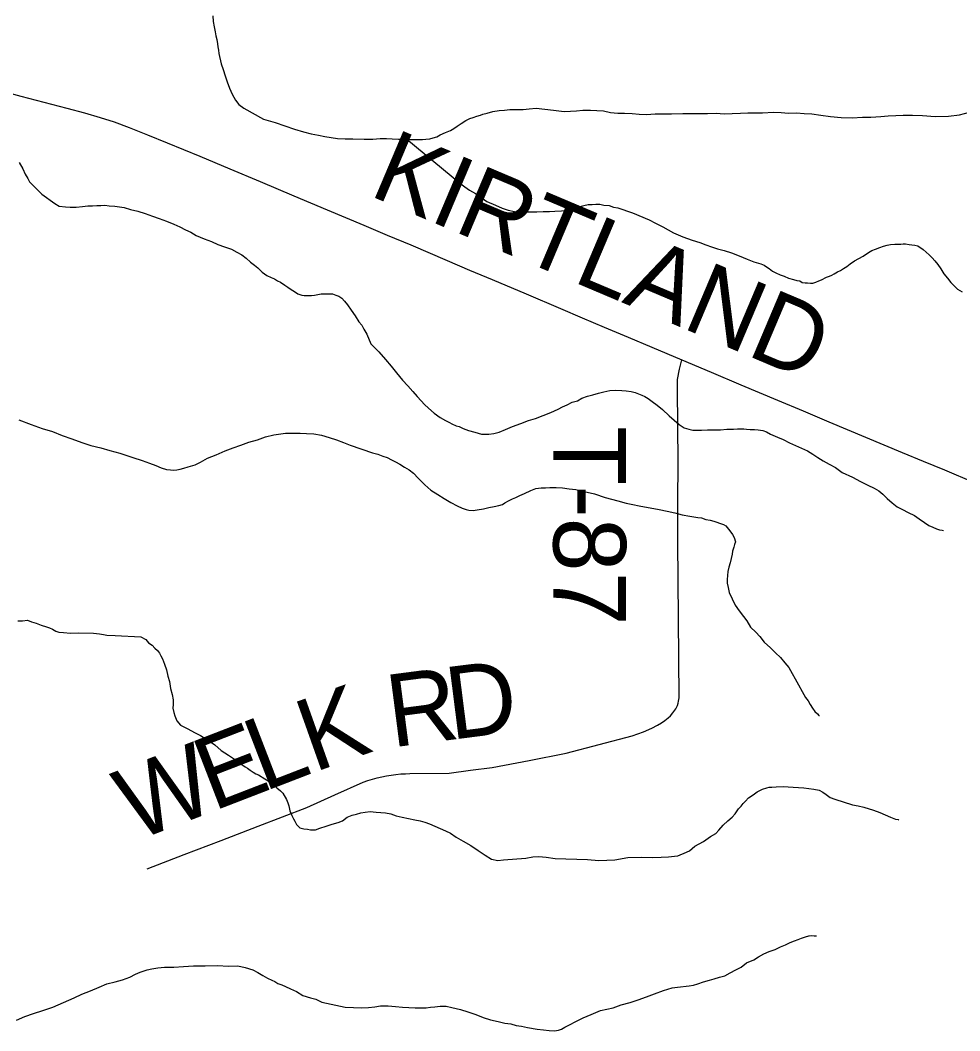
# Model space of a CAD drawing. Extents: x 103424 to 286016, y 38711 to 110967.
# Drawn here: x 120420 to 124329, y 102278 to 106482 of the extents above; entities that cross this region are included whole.
import ezdxf

# ---------------------------------------------------------------- set-up
doc = ezdxf.new("R2010")
doc.units = 0
for name, color, linetype in [('GM_X_County_Road', 7, 'Continuous'), ('GM_X_County_Road_Text', 7, 'Continuous'), ('GM_X_Minor_River', 7, 'Continuous'), ('GM_X_Township_Road', 7, 'Continuous'), ('GM_X_Township_Road_Text', 7, 'Continuous')]:
    doc.layers.add(name, color=color, linetype=linetype)

msp = doc.modelspace()

# ---------------------------------------------------------------- linework, layer by layer
at = {"layer": 'GM_X_County_Road'}
msp.add_lwpolyline([(120309.2, 106195.9), (120423.4, 106166), (120518.9, 106141.2), (120614.3, 106116.3), (120687.6, 106096.5), (120752.3, 106077.6), (120811.6, 106058.5), (120873.7, 106034.9), (120949.3, 106004.4), (121031.4, 105971.4), (121167, 105916.1), (121292.6, 105863.2), (121418.1, 105810.4), (121558, 105751.8), (121697.9, 105693.1), (121850, 105629.1), (121947.5, 105588.1), (122045.1, 105547), (122196.9, 105482.3), (122290, 105442.6), (122383.1, 105402.9), (122525.3, 105343), (122667.4, 105283), (122758.8, 105244), (122850.2, 105205.1), (122949, 105163.6), (123047.9, 105122.1), (123172.5, 105069.5), (123295.3, 105017.4), (123418.2, 104965.3), (123570.4, 104901.4), (123677.7, 104856.4), (123785, 104811.3), (123937.3, 104747.8), (124089.7, 104684.2), (124177.4, 104647.5), (124265.2, 104610.9), (124389, 104559.2)], dxfattribs=at)
at = {"layer": 'GM_X_Minor_River'}
for points in [[(121221, 106499.9), (121223.3, 106475.6), (121227.6, 106453.5), (121231.8, 106433.3), (121234, 106417.2), (121238.3, 106401), (121240.5, 106382.9), (121242.7, 106370.8), (121244.8, 106356.7), (121247, 106342.6), (121255.6, 106300.2), (121264, 106276.1), (121272.3, 106249.9), (121280.7, 106225.8), (121291.1, 106199.6), (121301.5, 106173.4), (121315.9, 106149.3), (121330.3, 106131.3), (121350.6, 106115.4), (121432, 106069.7), (121480.6, 106056.1), (121521.2, 106042.3), (121561.7, 106028.6), (121598.2, 106016.8), (121630.6, 106009.1), (121661, 106003.3), (121687.3, 105997.5), (121713.6, 105993.7), (121739.9, 105989.9), (121772.2, 105988.2), (121804.6, 105988.6), (121851, 105987), (121887.4, 105987.4), (121917.7, 105989.7), (121943.9, 105990), (121968.2, 105988.2), (121994.5, 105986.4), (122014.6, 105986.6), (122028.8, 105986.8), (122038.9, 105984.8), (122057.1, 105985), (122073.2, 105985.2), (122093.4, 105985.4), (122107.5, 105987.5), (122123.7, 105987.7), (122137.8, 105991.9), (122153.9, 105996.1), (122167.9, 106004.3), (122190, 106014.6), (122210.1, 106022.9), (122224.2, 106031.1), (122238.2, 106041.4), (122254.3, 106051.6), (122274.3, 106063.9), (122290.4, 106072.2), (122304.5, 106076.4), (122320.5, 106082.6), (122334.6, 106086.8), (122344.7, 106090.9), (122362.8, 106095.1), (122387, 106101.4), (122413.2, 106105.7), (122435.4, 106108), (122457.6, 106110.2), (122479.8, 106110.4), (122512.1, 106110.7), (122538.3, 106113), (122566.6, 106115.3), (122639.4, 106108), (122661.6, 106104.1), (122683.9, 106102.3), (122710.1, 106102.6)], [(122710.1, 106102.6), (122734.3, 106104.9), (122760.6, 106107.2), (122792.9, 106107.5), (122819.2, 106105.7), (122847.5, 106104), (122875.8, 106098.2), (122906.2, 106094.5), (122934.4, 106094.8), (122966.8, 106093), (122995.1, 106091.3), (123025.4, 106089.6), (123061.7, 106092), (123096, 106092.3), (123130.4, 106092.7), (123176.8, 106093.1), (123211.2, 106093.5), (123245.5, 106093.8), (123279.8, 106094.1), (123316.2, 106094.5), (123348.5, 106092.8), (123382.8, 106093.2), (123417.1, 106095.5), (123447.4, 106095.8), (123475.7, 106096.1), (123508, 106096.4), (123554.4, 106098.9), (123586.8, 106097.2), (123617.1, 106095.5), (123649.4, 106095.8), (123681.8, 106094.1), (123714.1, 106092.4), (123750.5, 106086.7), (123791, 106081.1), (123835.5, 106077.5), (123881.9, 106075.9), (123924.3, 106078.3), (123958.6, 106078.7), (124001, 106081.1), (124031.3, 106083.5), (124063.6, 106085.8), (124093.9, 106086.1), (124132.3, 106086.5), (124174.7, 106084.9), (124227.3, 106081.4), (124281.8, 106081.9), (124328.2, 106088.4), (124390.6, 106105.2)], [(122028.8, 105986.8), (122253.1, 105801.1), (122269.4, 105789.2), (122289.8, 105775.2), (122314.2, 105761.4), (122336.6, 105745.4), (122361, 105727.5), (122397.6, 105711.7), (122426, 105699.9), (122450.3, 105692), (122476.6, 105686.2), (122498.9, 105684.4), (122521.1, 105684.6), (122543.3, 105684.9), (122569.6, 105685.1), (122595.8, 105685.4), (122622.1, 105685.6), (122644.3, 105687.9), (122672.5, 105688.2), (122690.7, 105690.4), (122706.8, 105694.6), (122718.9, 105698.7), (122733, 105702.9), (122749.1, 105707.1), (122765.2, 105711.3), (122783.3, 105715.5), (122799.5, 105715.7), (122815.6, 105715.9), (122831.8, 105716), (122848, 105712.1), (122870.2, 105710.3), (122888.5, 105704.5), (122906.7, 105700.6), (122927, 105694.7), (122947.2, 105686.9), (122967.5, 105681), (123036.5, 105651.4), (123062.9, 105637.5), (123093.4, 105621.7), (123138.1, 105597.9), (123176.7, 105580.1), (123215.3, 105566.3), (123247.7, 105556.5), (123272, 105546.7), (123296.4, 105538.8), (123320.7, 105531), (123349.1, 105523.2), (123379.5, 105513.4), (123411.9, 105501.6), (123444.4, 105487.8), (123472.8, 105476), (123501.2, 105468.2), (123515.4, 105462.2), (123525.6, 105456.3), (123535.7, 105448.3), (123550, 105438.4), (123564.2, 105430.4), (123582.5, 105422.5), (123598.7, 105416.6), (123617, 105408.7), (123637.3, 105402.9), (123651.5, 105399), (123663.6, 105397.1), (123673.8, 105391.1), (123685.9, 105389.2), (123696, 105389.3), (123708.1, 105387.4), (123718.2, 105387.5), (123730.3, 105391.7), (123742.4, 105397.8), (123754.4, 105402), (123774.5, 105412.3), (123786.6, 105416.5), (123796.6, 105420.6), (123806.7, 105426.8), (123820.7, 105435), (123832.7, 105441.2), (123844.8, 105449.4), (123858.8, 105457.6), (123872.8, 105467.8), (123890.9, 105480.1), (123927, 105500.7), (123949, 105515), (123963.1, 105523.3), (123979.2, 105529.5), (123997.3, 105535.7), (124011.3, 105541.9), (124027.4, 105546.1), (124041.6, 105548.3), (124059.7, 105550.5), (124071.8, 105550.6), (124083.9, 105550.7), (124094, 105550.8), (124104.1, 105550.9), (124118.3, 105549), (124130.4, 105547.1), (124142.6, 105545.3), (124154.7, 105543.4)], [(120416.1, 105890), (120430.5, 105863.8), (120440.9, 105841.7), (120451.2, 105823.6), (120459.4, 105809.6), (120469.7, 105797.6), (120481.9, 105785.6), (120496.2, 105771.6), (120510.5, 105757.6), (120563.5, 105719.7), (120581.8, 105707.8), (120608.1, 105706), (120628.3, 105704.2), (120652.5, 105704.5), (120678.8, 105706.7), (120701, 105709), (120721.2, 105709.2), (120739.3, 105711.4), (120755.5, 105711.5), (120771.6, 105711.7), (120789.8, 105709.9), (120814.1, 105708.1), (120852.5, 105702.4), (120878.9, 105694.6), (120909.3, 105686.8), (120939.7, 105677), (120970.1, 105667.2), (120998.5, 105657.4), (121028.9, 105645.6), (121059.3, 105633.8), (121083.7, 105621.9), (121108.1, 105610), (121130.4, 105600.1), (121152.8, 105586.2), (121185.3, 105572.4), (121215.7, 105560.6), (121242.1, 105548.7), (121270.5, 105538.9), (121298.9, 105529.1), (121321.2, 105517.2), (121341.6, 105505.3), (121359.9, 105491.3), (121378.3, 105475.3), (121394.6, 105463.4), (121408.9, 105451.4), (121427.3, 105433.4), (121445.6, 105419.4), (121463.9, 105411.5), (121478.1, 105405.6), (121490.3, 105397.7), (121502.5, 105391.7), (121520.8, 105379.8), (121533, 105371.8), (121547.3, 105361.9), (121561.5, 105353.9), (121575.7, 105344), (121592, 105338.1), (121602.1, 105336.2), (121632.4, 105336.5), (121644.5, 105338.6), (121658.6, 105340.8), (121672.7, 105342.9), (121690.9, 105343.1), (121705, 105343.2), (121719.2, 105343.4), (121733.4, 105337.5), (121745.5, 105333.6), (121757.7, 105325.6), (121770, 105313.6), (121782.3, 105297.6), (121796.7, 105275.5), (121813.1, 105251.4), (121829.6, 105227.3), (121841.9, 105213.3), (121850.1, 105197.2)], [(124154.7, 105543.4), (124177.1, 105527.4), (124189.4, 105517.4), (124201.6, 105505.4), (124213.9, 105493.4), (124226.1, 105481.4), (124238.5, 105465.4), (124250.8, 105447.4), (124263.1, 105427.3), (124277.5, 105409.2), (124291.8, 105391.2), (124306.1, 105377.2), (124320.4, 105363.2), (124338.7, 105351.3)], [(121850.1, 105197.2), (121862.5, 105175.1), (121879.1, 105134.9), (121911.8, 105102.9), (121940.5, 105070.9), (121963, 105042.8), (121985.5, 105014.8), (122010.1, 104984.7), (122032.6, 104960.7), (122053.1, 104936.7), (122071.5, 104916.7), (122087.9, 104898.6), (122102.2, 104882.6), (122118.5, 104868.6), (122143, 104846.7), (122167.5, 104828.7), (122189.8, 104816.8), (122206.1, 104808.9), (122216.2, 104803), (122234.5, 104795.1), (122246.7, 104791.1), (122262.9, 104783.2), (122285.2, 104775.4), (122311.6, 104767.6), (122340, 104759.7), (122370.3, 104760.1), (122390.4, 104762.3), (122412.6, 104768.5), (122438.7, 104778.9), (122468.9, 104791.3), (122503, 104803.8), (122535.2, 104816.2), (122563.4, 104824.6), (122627.7, 104849.5), (122657.9, 104863.9), (122675.9, 104874.2), (122696, 104882.5), (122716.1, 104892.8), (122738.3, 104899), (122756.3, 104909.3), (122780.5, 104917.6), (122802.6, 104923.9), (122826.8, 104930.2), (122848.9, 104936.5), (122873.1, 104940.8), (122897.3, 104943), (122923.6, 104941.3), (122941.8, 104939.4), (122962, 104937.6), (122978.2, 104933.8), (122992.4, 104927.8), (123006.6, 104921.9), (123018.8, 104916), (123033, 104908), (123049.3, 104896.1), (123069.7, 104880.1), (123092.1, 104862.2), (123120.7, 104836.2), (123141.1, 104818.2), (123161.5, 104800.2), (123181.9, 104786.3), (123202.2, 104780.5), (123218.4, 104776.6), (123234.5, 104776.7), (123254.7, 104776.9), (123279, 104777.2), (123305.2, 104777.4), (123333.5, 104777.7), (123359.7, 104780), (123388, 104780.3), (123404.1, 104782.5), (123418.3, 104782.6), (123430.4, 104782.7), (123442.5, 104780.8), (123456.7, 104778.9), (123474.9, 104779.1), (123491, 104777.3), (123509.2, 104775.4), (123525.5, 104769.5), (123541.7, 104759.6), (123570.2, 104747.8), (123594.5, 104737.9), (123620.9, 104724), (123696.1, 104690.4), (123718.4, 104676.5), (123738.8, 104662.6), (123761.2, 104648.7), (123785.6, 104634.8), (123812, 104620.9), (123840.5, 104601), (123883.1, 104581.2), (123915.7, 104563.3), (123946.1, 104547.5), (123972.5, 104535.6), (123992.9, 104523.7), (124009.2, 104509.7), (124027.6, 104491.8), (124048, 104473.8), (124068.4, 104457.8), (124090.7, 104445.9), (124115.1, 104434)], [(120414.4, 104819.4), (120465.1, 104799.7), (120511.8, 104784), (120554.3, 104770.3), (120594.9, 104754.5), (120635.5, 104740.8), (120676, 104725), (120714.6, 104713.3), (120755.1, 104703.6), (120793.6, 104691.9), (120834.1, 104680.2), (120888.9, 104662.5), (120927.4, 104650.8), (120957.8, 104639), (120984.2, 104629.1), (121006.5, 104619.3), (121028.8, 104613.4), (121045, 104611.6), (121059.1, 104609.7), (121071.2, 104611.8), (121085.3, 104614), (121101.4, 104618.2), (121119.6, 104624.4), (121147.7, 104632.8), (121169.8, 104643.1), (121199.9, 104659.6), (121236.1, 104674.1), (121272.3, 104690.6), (121306.5, 104703), (121338.7, 104713.4), (121370.8, 104725.9), (121407.1, 104736.3), (121441.3, 104748.8), (121475.5, 104757.2), (121523.9, 104763.8), (121556.2, 104764.1), (121584.5, 104764.4), (121610.8, 104762.6), (121641.1, 104760.9), (121673.5, 104755.1), (121705.9, 104745.4), (121736.3, 104735.6), (121764.7, 104725.8)], [(121764.7, 104725.8), (121793.1, 104713.9), (121886.4, 104682.5), (121908.7, 104676.7), (121929, 104668.8), (121947.2, 104662.9), (121965.5, 104653), (121981.8, 104645.1), (122000.1, 104635.2), (122018.4, 104623.2), (122038.7, 104611.3), (122057, 104597.4), (122075.5, 104577.4), (122104.1, 104549.4), (122128.6, 104527.4), (122157, 104509.5), (122183.5, 104491.6), (122212, 104475.7), (122238.4, 104461.8), (122258.7, 104451.9), (122274.9, 104446), (122287.1, 104444.1), (122305.3, 104442.3), (122321.4, 104444.5), (122347.6, 104448.8), (122369.7, 104455), (122391.9, 104459.3), (122412.1, 104463.5), (122426.2, 104467.7), (122436.2, 104473.9), (122452.2, 104482.1), (122468.3, 104490.4), (122482.4, 104496.6), (122498.4, 104504.8), (122518.5, 104513.1), (122544.7, 104525.5), (122564.8, 104533.7), (122586.9, 104536), (122605.1, 104536.2), (122623.3, 104538.4), (122649.5, 104538.6), (122675.8, 104536.9), (122704.1, 104533.1), (122732.5, 104529.4), (122766.9, 104521.6), (122809.4, 104511.9), (122854, 104496.2), (122906.7, 104482.6), (122941.1, 104472.8), (122969.5, 104467.1), (122995.8, 104461.3), (123078.8, 104445.9), (123111.2, 104440.2), (123143.6, 104432.4), (123174, 104424.7), (123206.4, 104418.9), (123238.8, 104413.2), (123254.9, 104411.3), (123273.2, 104405.4), (123291.4, 104401.6), (123305.6, 104397.7), (123317.8, 104393.8), (123329.9, 104389.9), (123346.1, 104384), (123356.3, 104378), (123372.7, 104358), (123383, 104341.9), (123391.2, 104329.9), (123395.5, 104311.7), (123391.5, 104301.6), (123389.7, 104289.5), (123383.8, 104273.2), (123381.9, 104261.1), (123378.1, 104242.9), (123374.2, 104224.7), (123368.4, 104206.4), (123364.6, 104188.2), (123362.7, 104172), (123360.9, 104155.9), (123361.1, 104139.7), (123365.4, 104121.6), (123369.6, 104101.4), (123382, 104075.3), (123394.5, 104049.1), (123410.9, 104025.1), (123429.4, 104001), (123443.7, 103983), (123458.2, 103956.9), (123480.6, 103936.9), (123497, 103918.9), (123515.4, 103894.8), (123542, 103870.8), (123562.4, 103850.8), (123582.8, 103830.9), (123601.3, 103808.8), (123617.7, 103788.8), (123632.1, 103764.7), (123644.4, 103742.6), (123687.8, 103664.2), (123698, 103650.2), (123706.3, 103636.1)], [(124115.1, 104434), (124141.5, 104422.2), (124159.8, 104408.2), (124182.2, 104392.3), (124200.6, 104380.4), (124216.8, 104372.4), (124233, 104366.5), (124245.2, 104362.6), (124255.3, 104360.7), (124261.4, 104358.7)], [(120410, 103983.1), (120430.2, 103983.3), (120450.4, 103985.6), (120466.6, 103979.7), (120486.8, 103973.8), (120507.1, 103965.9), (120529.4, 103958.1), (120541.6, 103954.1), (120553.8, 103948.2), (120568, 103940.3), (120580.2, 103936.3), (120600.4, 103934.5), (120628.7, 103932.8), (120663, 103933.1), (120725.7, 103931.7), (120749.9, 103929.9), (120766.1, 103926.1), (120780.3, 103924.2), (120814.6, 103922.5), (120921.8, 103917.5), (120942.1, 103905.6), (120954.4, 103891.6), (120968.6, 103881.6), (120980.9, 103869.6), (120991.1, 103859.6), (120999.3, 103849.6), (121005.5, 103837.6), (121011.7, 103825.5), (121020, 103803.4), (121028.4, 103779.2), (121034.8, 103753), (121041.1, 103730.8), (121045.4, 103702.6), (121051.8, 103676.4), (121056.1, 103654.2), (121056.3, 103636.1), (121054.5, 103619.9), (121058.7, 103601.8), (121062.9, 103587.6), (121071.2, 103567.5), (121087.6, 103549.5), (121105.9, 103539.6), (121118.1, 103533.7), (121130.3, 103527.7), (121148.6, 103517.8), (121170.9, 103505.9), (121199.4, 103488), (121230, 103468.1), (121256.5, 103444.1), (121287, 103424.2), (121307.4, 103410.3), (121323.7, 103398.4), (121342, 103386.4), (121356.2, 103376.5), (121366.4, 103370.5), (121376.6, 103362.5), (121388.8, 103354.6), (121401, 103346.6), (121411.2, 103342.7), (121437.6, 103326.8), (121455.9, 103314.8), (121472.2, 103302.9), (121488.5, 103288.9), (121502.8, 103276.9), (121513, 103266.9), (121527.5, 103240.8), (121533.7, 103226.7), (121537.9, 103214.6), (121542.2, 103192.5), (121550.5, 103174.4), (121556.7, 103160.3), (121562.9, 103150.3), (121569.1, 103136.2), (121583.4, 103122.2), (121599.6, 103118.3), (121615.8, 103116.4), (121627.9, 103114.5), (121648.1, 103114.7)], [(123706.3, 103636.1), (123716.6, 103620.1), (123726.8, 103606.1), (123737, 103596.1), (123743.2, 103590.1), (123745.2, 103590.1)], [(121648.1, 103114.7), (121666.2, 103121), (121692.4, 103129.3), (121718.5, 103137.7), (121742.7, 103144), (121760.8, 103152.2), (121780.8, 103166.6), (121800.9, 103174.8), (121819, 103179.1), (121837.2, 103185.3), (121855.3, 103187.5), (121875.5, 103189.7), (121901.7, 103188), (121919.9, 103186.1), (121940.2, 103184.3), (121962.4, 103180.5), (121984.7, 103172.6), (122009.1, 103166.8), (122035.4, 103161), (122061.7, 103155.2), (122084, 103151.4), (122104.2, 103145.5), (122122.5, 103139.6), (122144.8, 103129.8), (122167.1, 103119.9), (122189.5, 103110), (122209.8, 103100.1), (122234.2, 103084.2), (122262.7, 103066.3), (122295.2, 103048.5), (122325.7, 103028.6), (122354.3, 103008.6), (122380.7, 102992.7), (122407, 102986.9), (122431.2, 102989.2), (122524.1, 102996.2), (122552.3, 103002.5), (122578.5, 103002.8), (122608.8, 103001.1), (122645.3, 102995.4), (122689.7, 102993.8), (122736.2, 102992.2), (122780.6, 102990.7), (122827.1, 102987.1), (122893.8, 102989.8), (122948.2, 102998.4), (123006.7, 103001), (123051.2, 102999.4), (123087.5, 102999.8), (123117.8, 103002.1), (123142, 103004.4), (123156.1, 103006.5), (123166.2, 103010.6), (123182.3, 103016.9), (123204.4, 103027.2), (123226.4, 103045.6), (123262.5, 103066.2), (123292.5, 103086.6), (123314.6, 103099), (123326.6, 103113.2), (123344.5, 103133.6), (123364.5, 103152), (123382.5, 103166.3), (123394.5, 103180.6), (123408.4, 103200.9), (123420.3, 103213.2), (123428.3, 103223.3), (123438.3, 103233.5), (123450.2, 103247.8), (123470.3, 103260.1), (123486.3, 103272.4), (123508.4, 103282.7), (123526.5, 103289), (123536.6, 103291.1), (123546.7, 103291.2), (123564.8, 103293.4), (123595.1, 103293.7), (123635.5, 103292.1), (123680, 103288.5), (123722.5, 103282.8), (123744.8, 103279), (123759, 103271.1), (123773.2, 103261.1), (123789.5, 103249.2), (123809.8, 103241.3), (123882.8, 103217.8), (123907.1, 103214), (123929.4, 103208.1), (123969.9, 103196.4), (123996.3, 103186.6), (124018.6, 103176.7), (124040.9, 103166.8), (124061.2, 103158.9), (124073.4, 103157), (124075.4, 103155)], [(123154.4, 102459.1), (123202.8, 102465.6), (123221, 102467.8), (123239.1, 102474.1), (123263.2, 102482.4), (123287.4, 102488.7), (123307.5, 102495), (123329.6, 102501.3), (123351.8, 102507.5), (123373.9, 102519.9), (123398, 102532.2), (123420.1, 102542.5), (123442.1, 102560.9), (123472.2, 102573.4), (123492.3, 102585.7), (123514.3, 102598), (123536.4, 102608.3), (123560.6, 102616.7), (123582.7, 102627), (123604.8, 102635.3), (123622.9, 102645.6), (123641, 102651.8), (123657, 102658), (123671.1, 102664.2), (123687.2, 102668.4), (123701.3, 102672.6), (123703.3, 102672.6), (123713.4, 102674.7), (123723.5, 102672.8), (123733.6, 102672.9)], [(120405.1, 102322.7), (120439.2, 102337.2), (120475.4, 102349.7), (120513.7, 102362.2), (120555.9, 102376.7), (120600.1, 102395.4), (120644.3, 102416), (120676.5, 102430.5), (120712.7, 102445), (120748.8, 102459.4), (120781, 102473.9), (120815.2, 102482.3), (120845.4, 102490.7), (120875.6, 102501.1), (120899.7, 102513.5), (120919.8, 102521.7), (120935.9, 102528), (120948, 102532.1), (120968.1, 102536.4), (120992.3, 102540.6), (121020.5, 102542.9), (121058.9, 102543.3), (121099.3, 102545.7), (121141.7, 102548.2), (121190.1, 102548.7), (121240.6, 102549.2), (121287.1, 102547.6), (121325.5, 102548), (121355.8, 102542.2), (121388.3, 102532.5), (121408.6, 102520.5), (121428.9, 102508.6), (121449.3, 102496.7), (121467.5, 102488.8), (121479.7, 102482.9), (121491.9, 102474.9), (121508.2, 102469), (121524.4, 102463.1), (121544.7, 102453.2), (121569.1, 102441.3), (121595.5, 102425.4), (121628, 102415.6), (121650.2, 102409.8), (121674.6, 102397.9), (121771.8, 102376.7), (121806.2, 102375), (121840.5, 102373.3), (121868.8, 102375.6), (121895, 102377.9), (121919.2, 102382.2), (121951.5, 102382.5), (121981.9, 102378.8), (122010.1, 102377), (122036.4, 102375.3), (122062.7, 102373.5), (122089, 102373.8), (122109.2, 102374), (122127.3, 102376.2), (122145.5, 102378.4), (122167.7, 102380.6), (122191.9, 102380.9), (122216.2, 102375), (122252.6, 102367.3), (122283, 102357.5), (122315.5, 102345.7), (122345.9, 102333.9), (122376.3, 102324.1), (122408.8, 102316.4), (122437.1, 102310.6), (122461.4, 102306.8), (122483.7, 102300.9), (122505.9, 102297.1), (122530.2, 102291.3), (122570.7, 102285.6), (122597, 102281.9), (122621.2, 102280.1), (122643.5, 102278.3), (122659.6, 102280.5), (122671.7, 102284.6), (122685.7, 102292.8), (122705.8, 102303.1), (122731.9, 102317.5), (122762, 102332), (122796.2, 102346.5), (122834.4, 102363), (122886.8, 102373.6), (122921, 102386.1), (122957.2, 102396.5), (122991.4, 102407), (123025.6, 102419.4), (123059.8, 102431.9), (123096, 102446.4), (123132.2, 102456.9), (123154.4, 102459.1)]]:
    msp.add_lwpolyline(points, dxfattribs=at)
at = {"layer": 'GM_X_Township_Road'}
msp.add_lwpolyline([(120948.2, 102951.8), (121102.2, 103011.1), (121256.3, 103070.4), (121410.4, 103129.7), (121511.3, 103168.5), (121612.2, 103207.3), (121729.7, 103259.8), (121847.2, 103312.3), (121866.4, 103318.9), (121885.3, 103324.9), (121904.7, 103330.2), (121924.3, 103334.9), (121943.9, 103338.8), (121963.6, 103342.1), (121983.5, 103344.6), (122003.3, 103346.5), (122023.5, 103347.7), (122041.1, 103348.1), (122205, 103349.9), (122294.1, 103361.7), (122383.2, 103373.6), (122537.2, 103403.1), (122691.1, 103432.6), (122828.8, 103468.9), (122966.5, 103505.2), (123013.2, 103522.2), (123047.7, 103537.6), (123071.1, 103548.9), (123088.2, 103558.6), (123101.8, 103568.4), (123115.4, 103579.9), (123125, 103588.7), (123135.6, 103600.1), (123148.1, 103617), (123151.2, 103622.6), (123155.5, 103631.7), (123157.9, 103640.3), (123159.5, 103648.6), (123161.3, 103663), (123159.9, 103828.1), (123158.6, 103993.1), (123157.2, 104152.4), (123155.9, 104311.7), (123156.4, 104476.7), (123156.9, 104641.8), (123154.8, 104948.9), (123155.5, 104987.6), (123162.6, 105029.5), (123172.5, 105069.5)], dxfattribs=at)

# ---------------------------------------------------------------- texts
at = {"layer": 'GM_X_County_Road_Text'}
msp.add_text('KIRTLAND', height=301.87, rotation=337.0624, dxfattribs=at).set_placement((121865.7, 105755.3))
at = {"layer": 'GM_X_Township_Road_Text'}
for s, height, rotation, p in [('T-87', 301.87, 270, (122638.6, 104793.8)), ('R', 301.9, 7.401, (121966.1, 103456.4)), ('D', 301.9, 7.2208, (122211.7, 103488.3)), ('K', 301.9, 19.5489, (121641.3, 103352)), ('L', 301.9, 21.1098, (121432.7, 103271.5)), ('E', 301.9, 21.1398, (121222.1, 103190.1)), ('W', 301.9, 21.1402, (120895.9, 103063.9))]:
    msp.add_text(s, height=height, rotation=rotation, dxfattribs=at).set_placement(p)

doc.saveas('drawing.dxf')
